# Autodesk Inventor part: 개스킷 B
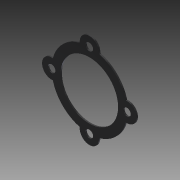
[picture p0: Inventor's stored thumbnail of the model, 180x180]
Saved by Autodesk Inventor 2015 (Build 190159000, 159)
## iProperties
Created: 2020-03
Part Number: 개스킷 B
Material: 고무
Document SubType Name: Modeling
Designer: mduedu
Density: 0.93 g/cm^3
Mass: 1.13966 g
Surface Area: 28.6179 cm^2
Volume: 1.22544 cm^3
Appearance: 고무 - 검은색 - 버전 1.1
Author: mduedu
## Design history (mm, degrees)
sketch "스케치1" dims "d1" = 55
  geometry: C1 r 21 at (0, 0); C2 r 7 at (0, 27.5); C3 r 7 at (-23.816, -13.75); C4 r 7 at (23.816, -13.75); 2 further points
  constraints: 4 centre point, 2 coincident, 2 vertical alignment, 9 other
  dimensions: "d0" = 42 diameter of C1; "d2" = 14 diameter of C2; "d5" = 360 deg dimension on point (0, 0) C2.centre (derived)
extrude "돌출1" new body sketch "스케치1" distance "d7" = 1; taper "d8" = 0 deg
extrude "돌출3" join sketch "스케치1" stored distance "d19" = 10; taper "d20" = 0 deg
fillet "모깎기1" dims "d11" = 1
extrude "돌출2" cut sketch "스케치1" stored distance "d9" = 1; taper "d10" = 0 deg
sketch "스케치2"
  geometry: C1 r 21 at (0, 0) reference; A1 r 7 centre (0, 27.5) between (6.999, 27.373) and (-6.999, 27.373) reference; A2 r 27.5 centre (0, 0) between (26.609, 6.943) and (7.718, 26.395) reference; A3 r 1 centre (7.999, 27.355) between (6.999, 27.373) and (7.718, 26.395) reference; A4 r 7 centre (0, 27.5) between (6.999, 27.373) and (-6.999, 27.373) reference; A5 r 1 centre (-7.999, 27.355) between (-7.718, 26.395) and (-6.999, 27.373) reference; A6 r 7 centre (0, -27.5) between (-6.943, -26.609) and (6.943, -26.609) reference; A7 r 7 centre (-27.5, 0) between (-26.609, 6.943) and (-26.609, -6.943) reference; A8 r 7 centre (27.5, 0) between (26.609, -6.943) and (26.609, 6.943) reference; A9 r 27.5 centre (0, 0) between (-26.609, -6.943) and (-6.943, -26.609) reference; A10 r 27.5 centre (0, 0) between (6.943, -26.609) and (26.609, -6.943) reference; A11 r 27.5 centre (0, 0) between (-7.718, 26.395) and (-26.609, 6.943) reference; 4 further points
hole "구멍1" sketch "스케치2" diameter "d12" = 5.5; stored, may be unused: countersink angle "d16" = 90 deg, drill point angle "d18" = 118 deg; dims "d13" = 6, "d14" = 4, "d15" = 2, "d17" = 8
node "솔리드1"
pattern_circular "원형 패턴1" dims angle "d22" = 360 deg
node "투영된 루프1"
